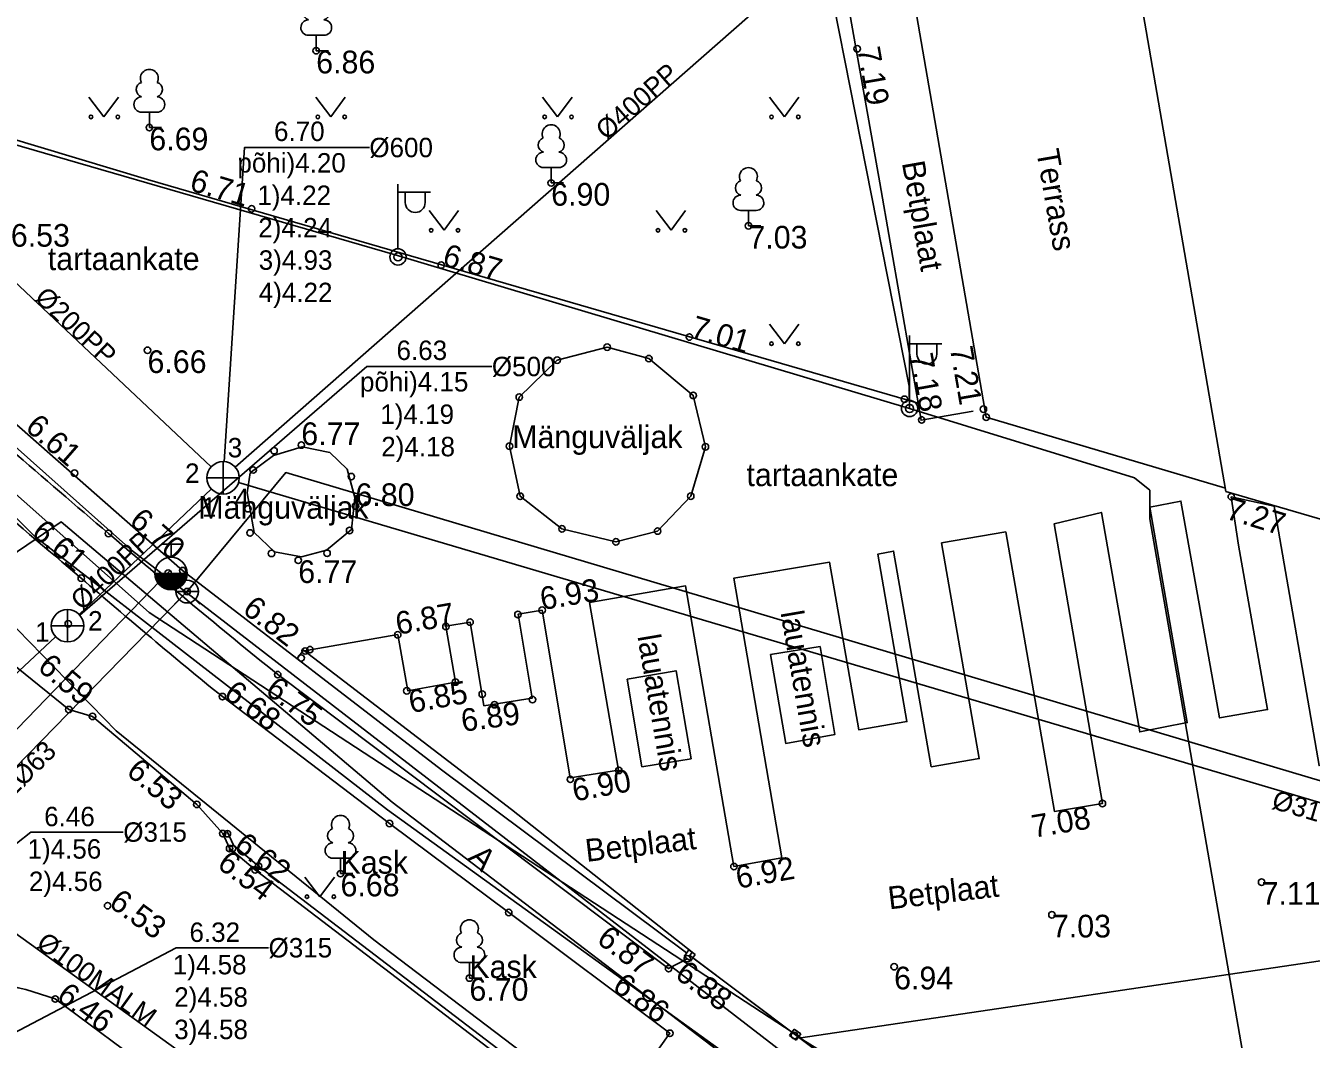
# Model space of a CAD drawing. Extents: x 473307 to 473719, y 6532843 to 6533381.
# Drawn here: x 473506.36 to 473546.03, y 6532972 to 6533003.28 of the extents above; entities that cross this region are included whole.
import ezdxf

# ---------------------------------------------------------------- set-up
doc = ezdxf.new("R2010")
doc.units = 0
for name, color, linetype in [('AED', 7, 'Continuous'), ('Default', 7, 'Continuous'), ('HALJASTUS', 7, 'Continuous'), ('HOONE', 7, 'Continuous'), ('HOONEDET', 7, 'Continuous'), ('KKAEV_NR', 7, 'Continuous'), ('KORGUS', 7, 'Continuous'), ('KPKAABEL', 7, 'Continuous'), ('MPKAABEL', 7, 'Continuous'), ('PIIR', 7, 'Continuous'), ('POST', 7, 'Continuous'), ('PUU', 7, 'Continuous'), ('RAJATIS', 7, 'Continuous'), ('SKKAEV', 7, 'Continuous'), ('SKKAEV_NR', 7, 'Continuous'), ('SKTRASS', 7, 'Continuous'), ('SKTRASS_TEKST', 7, 'Continuous'), ('TEE', 7, 'Continuous'), ('VKAEV', 7, 'Continuous'), ('VTRASS', 7, 'Continuous'), ('VTRASS_TEKST', 7, 'Continuous')]:
    doc.layers.add(name, color=color, linetype=linetype)

# ---------------------------------------------------------------- blocks, each defined once
blk = doc.blocks.new('LEHTP1')
at = {"layer": 'Default'}
for p, q in [((0.48, 0.95), (-0.48, 0.95)), ((0, 0), (0, 0.95)), ((0.76, 0), (0, 0))]:
    blk.add_line(p, q, dxfattribs=at)
for centre, radius, start, end in [((0, 3.04), 0.554, 332.5799, 207.4201), ((-0.34, 2.345), 0.465, 109.02174, 253.14154), ((0.34, 2.345), 0.465, 286.85082, 70.98591), ((-0.475, 1.425), 0.475, 90.0016, 269.3953), ((0.475, 1.425), 0.475, 270.6047, 89.9984)]:
    blk.add_arc(centre, radius, start, end, dxfattribs=at)
blk = doc.blocks.new('MEPOST')
at = {"layer": 'Default'}
blk.add_circle((0, 0), 0.5, dxfattribs=at)
for start, end in [(0, 180), (180, 0)]:
    blk.add_arc((0, 0), 0.25, start, end, dxfattribs=at)
blk = doc.blocks.new('VAPOST')
at = {"layer": 'Default'}
for p, q in [((0, 0.5), (0, 4.5)), ((0, 4), (2, 4)), ((0.453, 3.358), (0.453, 4)), ((1.679, 3.358), (1.679, 4))]:
    blk.add_line(p, q, dxfattribs=at)
blk.add_arc((1.066, 3.358), 0.613, 180, 0, dxfattribs=at)
blk = doc.blocks.new('KAKAEV')
at = {"layer": 'Default'}
for p, q in [((0, -1), (0, 1)), ((-1, 0), (1, 0))]:
    blk.add_line(p, q, dxfattribs=at)
blk.add_circle((0, 0), 1, dxfattribs=at)
blk = doc.blocks.new('THYDRM')
at = {"layer": 'Default'}
for p, q in [((-0.6, 1.8), (0.6, 1.8)), ((0, 1), (0, 1.8)), ((-1, 0), (1, 0))]:
    blk.add_line(p, q, dxfattribs=at)
blk.add_circle((0, 0), 1, dxfattribs=at)
blk = doc.blocks.new('THYDRK')
at = {"layer": 'Default'}
blk.add_line((-1, 0), (1, 0), dxfattribs=at)
blk.add_circle((0, 0), 1, dxfattribs=at)
for radius in [0.965, 0.935, 0.901, 0.871, 0.836, 0.806, 0.772, 0.742, 0.707, 0.677, 0.642, 0.612, 0.578, 0.548, 0.513, 0.483, 0.449, 0.419, 0.384, 0.354, 0.319, 0.289, 0.255, 0.225, 0.19, 0.16, 0.126, 0.0956, 0.0656, 0.0356]:
    blk.add_arc((0, 0), radius, 180, 0, dxfattribs=at)
blk = doc.blocks.new('VESIIB')
at = {"layer": 'Default'}
for p, q in [((-0.7, 0), (0.7, 0)), ((-0.495, -0.495), (-0.774, -0.774)), ((0.495, -0.495), (0.774, -0.774))]:
    blk.add_line(p, q, dxfattribs=at)
blk.add_circle((0, 0), 0.7, dxfattribs=at)
blk = doc.blocks.new('MURU')
at = {"layer": 'Default'}
for p, q in [((-0.927, 1.213), (0, 0)), ((0, 0), (0.891, 1.213))]:
    blk.add_line(p, q, dxfattribs=at)
for centre in [(-0.802, 0), (0.856, 0)]:
    blk.add_circle(centre, 0.11, dxfattribs=at)
blk = doc.blocks.new('VARPOS')
at = {"layer": 'Default'}
for p, q in [((-0.25, 0.25), (-0.25, -0.25)), ((-0.25, 0.25), (0.25, 0.25)), ((0.25, 0.25), (0.25, -0.25)), ((-0.25, -0.25), (0.25, -0.25))]:
    blk.add_line(p, q, dxfattribs=at)

msp = doc.modelspace()

# ---------------------------------------------------------------- linework, layer by layer
at = {"layer": 'AED'}
for points in [[(473488.644, 6533006.098), (473492.383, 6533002.912), (473499.933, 6532996.364), (473511.2, 6532986.464), (473519.19, 6532980.316), (473526.747, 6532974.664)], [(473529.997, 6532972.215), (473526.947, 6532974.514)], [(473530.2, 6532972.069), (473530.991, 6532971.474)]]:
    msp.add_lwpolyline(points, dxfattribs=at)
at = {"layer": 'HOONE'}
msp.add_lwpolyline([(473585.831, 6533013.369), (473574.881, 6533011.486), (473566.132, 6533009.962), (473540.511, 6533005.576), (473543.395, 6532988.91), (473585.455, 6532976.623), (473588.828, 6532956.753), (473587.886, 6532956.595), (473589.164, 6532949.286), (473629.221, 6532956.166), (473626.335, 6532972.834), (473619.836, 6532974.765), (473602.305, 6532979.874), (473597.625, 6532979.18), (473590.334, 6532981.418), (473586.157, 6533005.917), (473587.084, 6533006.076)], close=True, dxfattribs=at)
at = {"layer": 'HOONEDET'}
msp.add_lwpolyline([(473540.509, 6533005.59), (473533.715, 6533004.411), (473535.999, 6532991.198), (473543.379, 6532989.006)], dxfattribs=at)
at = {"layer": 'KKAEV_NR'}
for points in [[(473505.175, 6532977.34), (473506.516, 6532978.395), (473509.368, 6532978.395)], [(473505.356, 6532971.855), (473510.999, 6532974.825), (473513.851, 6532974.825)]]:
    msp.add_lwpolyline(points, dxfattribs=at)
at = {"layer": 'KORGUS'}
for centre in [(473515.322, 6533002.51), (473532.016, 6533002.571), (473510.172, 6533000.136), (473522.573, 6532998.427), (473513.329, 6532997.63), (473528.659, 6532997.104), (473519.18, 6532995.894), (473526.836, 6532993.673), (473510.116, 6532993.263), (473524.298, 6532993.361), (473522.755, 6532992.957), (473525.587, 6532993.006), (473521.587, 6532991.82), (473526.957, 6532991.872), (473533.475, 6532991.752), (473535.91, 6532991.447), (473534.005, 6532991.113), (473535.999, 6532991.198), (473514.021, 6532990.164), (473514.862, 6532990.339), (473521.288, 6532990.304), (473527.332, 6532990.283), (473507.863, 6532989.474), (473513.376, 6532989.569), (473516.405, 6532989.365), (473516.534, 6532988.457), (473521.615, 6532988.757), (473521.616, 6532988.758), (473526.878, 6532988.76), (473543.56, 6532988.745), (473513.216, 6532988.374), (473516.352, 6532987.704), (473522.906, 6532987.753), (473525.857, 6532987.684), (473508.914, 6532987.611), (473513.279, 6532987.627), (473524.572, 6532987.351), (473513.94, 6532986.995), (473515.656, 6532987), (473514.768, 6532986.782), (473508.071, 6532986.229), (473510.754, 6532986.383), (473511.2, 6532986.464), (473511.34, 6532985.817), (473521.547, 6532985.11), (473522.292, 6532985.244), (473507.67, 6532984.823), (473519.324, 6532984.736), (473520.068, 6532984.871), (473517.836, 6532984.48), (473514.858, 6532983.767), (473514.98, 6532983.983), (473515.13, 6532984.025), (473514.133, 6532983.253), (473519.617, 6532983.024), (473512.426, 6532982.575), (473518.118, 6532982.753), (473520.445, 6532982.65), (473507.688, 6532982.175), (473520.823, 6532982.325), (473521.994, 6532982.482), (473508.418, 6532981.966), (473524.661, 6532980.298), (473523.163, 6532980.022), (473511.636, 6532979.25), (473539.582, 6532979.276), (473517.583, 6532978.66), (473512.435, 6532978.347), (473512.581, 6532978.344), (473512.649, 6532977.885), (473512.742, 6532977.882), (473513.434, 6532977.231), (473513.539, 6532977.344), (473516.072, 6532977.111), (473528.213, 6532977.333), (473544.495, 6532976.85), (473508.885, 6532976.122), (473521.261, 6532975.911), (473538.025, 6532975.842), (473526.197, 6532974.181), (473526.773, 6532974.485), (473533.155, 6532974.24), (473520.049, 6532973.889), (473507.269, 6532973.243), (473526.237, 6532972.185), (473530.08, 6532972.116)]:
    msp.add_circle(centre, 0.1, dxfattribs=at)
at = {"layer": 'KPKAABEL'}
msp.add_lwpolyline([(473552.428, 6532965.743), (473551.926, 6532964.369), (473550.859, 6532963.61), (473549.116, 6532963.304), (473547.25, 6532963.025), (473541.17, 6532963.479), (473534.383, 6532967.06), (473529.823, 6532970.204), (473517.524, 6532979.079), (473506.639, 6532987.521), (473501.292, 6532992.893), (473495.73, 6532998.121), (473498.407, 6533003.379)], dxfattribs=at)
at = {"layer": 'MPKAABEL'}
for points in [[(473592.161, 6532931.655), (473583.871, 6532934.989), (473574.572, 6532939.314), (473574.03, 6532940.034), (473574.304, 6532941.029), (473573.472, 6532940.172), (473563.473, 6532945.174), (473556.129, 6532949.371), (473546.422, 6532955.029), (473536.136, 6532961.464), (473535.978, 6532962.869), (473534.663, 6532962.568), (473525.661, 6532968.571), (473517.097, 6532975.071), (473509.151, 6532981.519), (473503.051, 6532987.775), (473502.694, 6532988.631), (473501.293, 6532988.874), (473494.528, 6532995.717), (473488.455, 6533001.872), (473481.096, 6533010.082), (473475.299, 6533017.476)], [(473529.543, 6533015.062), (473529.217, 6533014.704), (473529.477, 6533013.158), (473533.62, 6532992.155), (473533.632, 6532991.468)], [(473550.647, 6532974.134), (473550.491, 6532974.716), (473550.13, 6532974.982), (473530.273, 6532972.046), (473510.168, 6532985.169), (473499.773, 6532994.387), (473488.127, 6533008.236)], [(473488.425, 6533006.486), (473501.71, 6533000.864), (473517.757, 6532996.211), (473517.757, 6532996.211), (473517.757, 6532996.211), (473533.632, 6532991.468), (473540.569, 6532989.326), (473541.046, 6532988.945), (473541.043, 6532988.058), (473544.258, 6532969.621), (473543.338, 6532964.734), (473543.314, 6532964.208), (473547.196, 6532963.14), (473550.121, 6532963.651), (473551.828, 6532964.446), (473552.375, 6532965.735)], [(473502.694, 6532988.631), (473503.051, 6532987.775), (473509.151, 6532981.519), (473517.097, 6532975.071), (473525.661, 6532968.571), (473534.663, 6532962.568), (473535.978, 6532962.869)], [(473493.252, 6532975.715), (473497.24, 6532978.112), (473498.183, 6532979.06), (473499.269, 6532980.163), (473501.448, 6532982.423), (473503.504, 6532984.545), (473505.843, 6532986.884), (473507.45, 6532987.966), (473517.665, 6532979.32), (473529.752, 6532970.098), (473534.316, 6532966.914), (473541.139, 6532963.364), (473547.56, 6532962.777), (473549.436, 6532962.995), (473552.396, 6532963.548), (473552.501, 6532963.798), (473552.517, 6532963.893), (473552.555, 6532965.764)]]:
    msp.add_lwpolyline(points, dxfattribs=at)
at = {"layer": 'PIIR'}
msp.add_lwpolyline([(473486.57, 6533007.64), (473478.82, 6533017), (473548.5, 6533028.91), (473572.63, 6533056.43), (473618.6, 6533063.82), (473630.89, 6533065.72), (473654.16, 6532926.37), (473652.82, 6532924.82), (473637.7, 6532924.6), (473625.07, 6532926.73), (473607.63, 6532930.98), (473579.04, 6532941.93), (473554.34, 6532955.84), (473531.51, 6532970.21), (473509.62, 6532987.09)], close=True, dxfattribs=at)
msp.add_lwpolyline([(473455.33, 6533045.76), (473478.82, 6533017), (473486.57, 6533007.64), (473509.62, 6532987.09), (473531.51, 6532970.21), (473554.34, 6532955.84), (473579.04, 6532941.93), (473607.63, 6532930.98), (473625.07, 6532926.73), (473637.7, 6532924.6), (473652.82, 6532924.82), (473654.16, 6532926.37), (473664.64, 6532927.81), (473668.24, 6532906.4), (473641.69, 6532906.33), (473620.6, 6532909.02), (473600.1, 6532914.5), (473579.89, 6532922.16), (473559.95, 6532931.3), (473540.88, 6532942.28), (473521.95, 6532954.78), (473501.05, 6532969.5), (473492.55, 6532977.62), (473473.12, 6532997.79)], dxfattribs=at)
at = {"layer": 'RAJATIS'}
for points in [[(473530.986, 6533008.316), (473496.948, 6533002.512), (473502.486, 6533000.825), (473510.117, 6532998.537), (473533.9, 6532991.636)], [(473521.288, 6532990.304), (473521.616, 6532988.758), (473522.906, 6532987.753), (473524.572, 6532987.351), (473525.857, 6532987.684), (473526.878, 6532988.76), (473527.332, 6532990.283), (473526.957, 6532991.872), (473525.587, 6532993.006), (473524.298, 6532993.361), (473522.755, 6532992.957), (473521.587, 6532991.82), (473521.288, 6532990.304)], [(473514.872, 6532986.894), (473515.639, 6532987.098), (473516.408, 6532987.729), (473516.512, 6532988.718), (473516.276, 6532989.598), (473515.744, 6532990.107), (473514.891, 6532990.288), (473514.002, 6532990.013), (473513.279, 6532989.477), (473513.193, 6532988.865), (473513.411, 6532987.645), (473514.037, 6532987.039), (473514.872, 6532986.894)], [(473529.344, 6532983.875), (473529.812, 6532981.131), (473531.323, 6532981.403), (473530.872, 6532984.119), (473529.344, 6532983.875)], [(473524.914, 6532983.116), (473526.428, 6532983.373), (473526.891, 6532980.657), (473525.374, 6532980.409), (473524.914, 6532983.116)]]:
    msp.add_lwpolyline(points, dxfattribs=at)
at = {"layer": 'SKKAEV_NR'}
for points in [[(473512.48, 6532989.826), (473513.106, 6532999.522), (473516.961, 6532999.522)], [(473508.024, 6532985.089), (473516.887, 6532992.764), (473520.742, 6532992.764)]]:
    msp.add_lwpolyline(points, dxfattribs=at)
at = {"layer": 'SKTRASS'}
for points in [[(473512.824, 6532989.657), (473539.223, 6533012.85)], [(473496.314, 6533004.528), (473512.084, 6532989.67)], [(473508.008, 6532985.106), (473512.086, 6532988.983)], [(473512.927, 6532989.185), (473569.849, 6532972.334)], [(473501.485, 6532979.012), (473507.28, 6532984.421)]]:
    msp.add_lwpolyline(points, dxfattribs=at)
at = {"layer": 'TEE'}
for points in [[(473530.768, 6533009.4), (473532.71, 6532998.434), (473533.987, 6532991.105), (473535.593, 6532991.384)], [(473512.435, 6532978.347), (473511.636, 6532979.25), (473508.418, 6532981.966), (473507.688, 6532982.175), (473501.425, 6532987.243), (473499.631, 6532988.913), (473487.102, 6533001.693), (473485.602, 6533003.164)], [(473543.785, 6532987.254), (473544.677, 6532982.175), (473543.2, 6532981.92), (473542.007, 6532988.612), (473541.044, 6532988.425), (473542.199, 6532981.776), (473540.734, 6532981.487), (473539.551, 6532988.259), (473538.096, 6532987.908), (473539.582, 6532979.276), (473538.102, 6532979.032), (473536.598, 6532987.656), (473534.617, 6532987.321), (473535.784, 6532980.663), (473534.3, 6532980.41), (473533.138, 6532987.069), (473532.654, 6532986.975), (473533.548, 6532981.803), (473532.064, 6532981.553), (473531.164, 6532986.723), (473528.205, 6532986.23), (473529.693, 6532977.595), (473528.213, 6532977.333), (473526.72, 6532985.991), (473523.757, 6532985.483), (473524.653, 6532980.301)], [(473543.785, 6532987.254), (473543.56, 6532988.745)], [(473556.963, 6532984.802), (473556.963, 6532984.802), (473556.963, 6532984.802), (473556.963, 6532984.802), (473557.385, 6532982.357), (473555.863, 6532982.14), (473555.342, 6532985.275), (473554.052, 6532985.454), (473554.673, 6532981.893), (473553.208, 6532981.623), (473552.392, 6532986.183), (473551.893, 6532986.227), (473552.341, 6532983.523), (473550.847, 6532983.274), (473550.268, 6532986.692), (473548.72, 6532987.053), (473549.36, 6532983.022), (473547.91, 6532982.748), (473547.02, 6532987.68), (473546.53, 6532987.705), (473547.752, 6532980.694), (473546.271, 6532980.446), (473544.878, 6532988.45), (473543.56, 6532988.745)], [(473514.958, 6532983.986), (473517.837, 6532984.492), (473518.149, 6532982.753), (473519.616, 6532983.016), (473519.325, 6532984.745), (473520.074, 6532984.869), (473520.495, 6532982.294), (473521.986, 6532982.531), (473521.55, 6532985.117), (473522.29, 6532985.241), (473523.161, 6532980.065), (473524.653, 6532980.301)], [(473514.755, 6532983.786), (473514.93, 6532984.01), (473521.352, 6532979.088), (473525.421, 6532975.868)], [(473526.773, 6532974.485), (473526.197, 6532974.181), (473514.133, 6532983.253)], [(473524.055, 6532969.123), (473526.237, 6532972.185), (473521.261, 6532975.911), (473517.583, 6532978.66), (473512.426, 6532982.575)], [(473512.435, 6532978.347), (473512.649, 6532977.896), (473513.434, 6532977.231), (473524.055, 6532969.123)], [(473512.571, 6532978.411), (473512.771, 6532977.99), (473513.528, 6532977.348), (473524.142, 6532969.245)], [(473525.421, 6532975.868), (473525.421, 6532975.868), (473526.918, 6532974.688), (473526.846, 6532974.587), (473530.2, 6532972.069), (473538.549, 6532966.914)], [(473507.269, 6532973.243), (473516.735, 6532966.211), (473521.977, 6532962.129), (473526.063, 6532959.019), (473526.41, 6532958.663), (473523.968, 6532954.435), (473525.686, 6532952.96), (473528.95, 6532956.691), (473529.581, 6532956.846), (473534.188, 6532954.059), (473548.771, 6532944.84), (473558.935, 6532938.993), (473557.576, 6532936.09)]]:
    msp.add_lwpolyline(points, dxfattribs=at)
for centre, radius, start, end in [((473770.556, 6533295.366), 403.943, 228.50272, 229.63001), ((473743.589, 6533265.294), 365.166, 228.5237, 229.83718), ((473652.96, 6533154.812), 220.693, 229.25461, 231.01989), ((473622.721, 6533118.452), 175.007, 229.07152, 230.93278), ((473503.234, 6532962.081), 11.869, 70.1266, 88.5433)]:
    msp.add_arc(centre, radius, start, end, dxfattribs=at)
at = {"layer": 'VTRASS'}
for points in [[(473503.152, 6532977.438), (473511.34, 6532985.817), (473514.381, 6532989.489), (473570.194, 6532972.861), (473572.889, 6532980.294)], [(473502.577, 6532977.945), (473510.799, 6532986.444)], [(473503.731, 6532976.927), (473535.265, 6532954.21), (473555.891, 6532941.175), (473565.122, 6532936.508), (473600.672, 6532921.587), (473636.512, 6532914.617), (473674.923, 6532915.363), (473675.557, 6532915.427)]]:
    msp.add_lwpolyline(points, dxfattribs=at)

# ---------------------------------------------------------------- block references
at = {"layer": 'AED', "xscale": 0.5, "yscale": 0.5, "rotation": -35.542607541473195}
for p in [(473526.846, 6532974.587), (473530.099, 6532972.142)]:
    msp.add_blockref('VARPOS', p, dxfattribs=at)
at = {"layer": 'HALJASTUS', "xscale": 0.5, "yscale": 0.5}
for p in [(473508.771, 6533000.467), (473515.771, 6533000.467), (473522.771, 6533000.467), (473529.771, 6533000.467), (473519.271, 6532996.967), (473526.271, 6532996.967), (473529.771, 6532993.467), (473515.438, 6532976.399)]:
    msp.add_blockref('MURU', p, dxfattribs=at)
at = {"layer": 'POST', "xscale": 0.5, "yscale": 0.5}
for name, p in [('VAPOST', (473517.844, 6532996.145)), ('MEPOST', (473517.844, 6532996.145)), ('VAPOST', (473533.632, 6532991.468)), ('MEPOST', (473533.632, 6532991.468))]:
    msp.add_blockref(name, p, dxfattribs=at)
at = {"layer": 'PUU', "xscale": 0.5, "yscale": 0.5}
for p in [(473515.322, 6533002.51), (473510.172, 6533000.136), (473522.573, 6532998.427), (473528.659, 6532997.104), (473516.072, 6532977.111), (473520.049, 6532973.889)]:
    msp.add_blockref('LEHTP1', p, dxfattribs=at)
at = {"layer": 'SKKAEV', "xscale": 0.5, "yscale": 0.5}
for p in [(473512.448, 6532989.327), (473507.646, 6532984.762)]:
    msp.add_blockref('KAKAEV', p, dxfattribs=at)
at = {"layer": 'VKAEV', "xscale": 0.5, "yscale": 0.5}
for name, p in [('THYDRM', (473510.842, 6532986.376)), ('THYDRK', (473510.842, 6532986.376)), ('VESIIB', (473511.34, 6532985.817))]:
    msp.add_blockref(name, p, dxfattribs=at)

# ---------------------------------------------------------------- texts
at = {"layer": 'HOONE'}
msp.add_text('Terrass', height=0.7, rotation=279.8485, dxfattribs=at).set_placement((473537.54, 6532999.414))
at = {"layer": 'KKAEV_NR'}
for s, p in [('6.46', (473506.927, 6532978.575)), ('%%c315', (473509.368, 6532978.095)), ('1)4.56', (473506.413, 6532977.575)), ('2)4.56', (473506.456, 6532976.575)), ('6.32', (473511.411, 6532975.004)), ('%%c315', (473513.851, 6532974.525)), ('1)4.58', (473510.897, 6532974.004)), ('2)4.58', (473510.94, 6532973.004)), ('3)4.58', (473510.94, 6532972.004))]:
    msp.add_text(s, height=0.6, dxfattribs=at).set_placement(p)
at = {"layer": 'KORGUS'}
for s, p in [('6.86', (473515.322, 6533001.81)), ('6.69', (473510.172, 6532999.436)), ('6.90', (473522.573, 6532997.727)), ('6.53', (473505.899, 6532996.461)), ('7.03', (473528.659, 6532996.404)), ('6.66', (473510.116, 6532992.563)), ('6.77', (473514.862, 6532990.339)), ('6.80', (473516.534, 6532988.457)), ('6.77', (473514.768, 6532986.082)), ('6.68', (473516.072, 6532976.411)), ('7.11', (473544.495, 6532976.15)), ('7.03', (473538.025, 6532975.142)), ('6.70', (473520.049, 6532973.189)), ('6.94', (473533.155, 6532973.54))]:
    msp.add_text(s, height=0.7, dxfattribs=at).set_placement(p)
for s, rotation, p in [('7.19', 279.8115, (473532.016, 6533002.571)), ('6.71', 343.4743, (473511.38, 6532998.208)), ('6.87', 343.841, (473519.18, 6532995.894)), ('7.01', 343.9221, (473526.836, 6532993.673)), ('7.21', 279.8072, (473534.874, 6532993.331)), ('7.18', 280.1648, (473533.646, 6532993.114)), ('6.61', 318.8684, (473506.306, 6532990.833)), ('7.27', 342.8887, (473543.354, 6532988.076)), ('6.70', 318.9149, (473509.517, 6532987.932)), ('6.61', 319.4949, (473506.5, 6532987.571)), ('6.93', 9.4526, (473522.292, 6532985.244)), ('6.82', 322.4085, (473513.009, 6532985.19)), ('6.87', 9.9362, (473517.836, 6532984.48)), ('6.59', 319.8356, (473506.686, 6532983.428)), ('6.68', 322.7956, (473512.426, 6532982.575)), ('6.75', 323.0572, (473513.712, 6532982.694)), ('6.85', 10.2477, (473518.243, 6532982.064)), ('6.89', 7.6363, (473519.84, 6532981.487)), ('6.53', 319.8356, (473509.427, 6532980.199)), ('6.90', 10.4394, (473523.29, 6532979.334)), ('7.08', 9.3426, (473537.459, 6532978.217)), ('6.62', 322.9524, (473512.742, 6532977.882)), ('6.54', 322.9524, (473512.227, 6532977.326)), ('6.92', 10.0493, (473528.335, 6532976.644)), ('6.53', 324.0024, (473508.885, 6532976.122)), ('6.87', 323.0572, (473523.938, 6532975.004)), ('6.88', 323.1141, (473526.353, 6532973.925)), ('6.86', 323.1743, (473524.423, 6532973.544)), ('6.46', 323.3913, (473507.269, 6532973.243))]:
    msp.add_text(s, height=0.7, rotation=rotation, dxfattribs=at).set_placement(p)
at = {"layer": 'PUU'}
for p in [(473516.072, 6532977.111), (473520.049, 6532973.889)]:
    msp.add_text('Kask', height=0.7, dxfattribs=at).set_placement(p)
at = {"layer": 'RAJATIS'}
for p in [(473521.37, 6532990.244), (473511.683, 6532988.065)]:
    msp.add_text('Mänguväljak', height=0.7, dxfattribs=at).set_placement(p)
for rotation, p in [(279.8443, (473529.647, 6532985.171)), (279.6743, (473525.231, 6532984.44))]:
    msp.add_text('lauatennis', height=0.7, rotation=rotation, dxfattribs=at).set_placement(p)
at = {"layer": 'SKKAEV_NR'}
for s, p in [('6.70', (473514.019, 6532999.722)), ('%%C600', (473516.961, 6532999.222)), ('põhi)4.20', (473512.89, 6532998.749)), ('1)4.22', (473513.505, 6532997.749)), ('2)4.24', (473513.533, 6532996.749)), ('3)4.93', (473513.548, 6532995.749)), ('4)4.22', (473513.548, 6532994.749)), ('6.63', (473517.8, 6532992.964)), ('%%C500', (473520.742, 6532992.464)), ('põhi)4.15', (473516.672, 6532991.992)), ('1)4.19', (473517.3, 6532990.992)), ('3', (473512.592, 6532989.959)), ('2)4.18', (473517.329, 6532989.992)), ('2', (473511.273, 6532989.172)), ('4', (473512.806, 6532988.395)), ('1', (473511.793, 6532988.126)), ('2', (473508.282, 6532984.615)), ('1', (473506.645, 6532984.269))]:
    msp.add_text(s, height=0.6, dxfattribs=at).set_placement(p)
at = {"layer": 'SKTRASS_TEKST'}
for s, rotation, p in [('%%C400PP', 41.3003, (473524.277, 6532999.72)), ('%%C200PP', 316.7054, (473506.595, 6532994.841)), ('%%C400PP', 43.5506, (473508.094, 6532985.206)), ('%%C315PP', 343.509, (473544.774, 6532979.131))]:
    msp.add_text(s, height=0.6, rotation=rotation, dxfattribs=at).set_placement(p)
at = {"layer": 'TEE'}
for s, rotation, p in [('Betplaat', 280, (473533.393, 6532999.051)), ('Betplaat', 6.6667, (473523.665, 6532977.473)), ('A', 315.0259, (473519.996, 6532977.58)), ('Betplaat', 6.6667, (473533.005, 6532976.007))]:
    msp.add_text(s, height=0.7, rotation=rotation, dxfattribs=at).set_placement(p)
for p in [(473507.04, 6532995.738), (473528.6, 6532989.071)]:
    msp.add_text('tartaankate', height=0.7, dxfattribs=at).set_placement(p)
at = {"layer": 'VTRASS_TEKST'}
for s, rotation, p in [('PE%%C63', 44.9131, (473505.512, 6532979.014)), ('%%C100MALM', 324.1296, (473506.644, 6532974.861))]:
    msp.add_text(s, height=0.6, rotation=rotation, dxfattribs=at).set_placement(p)

doc.saveas('drawing.dxf')
